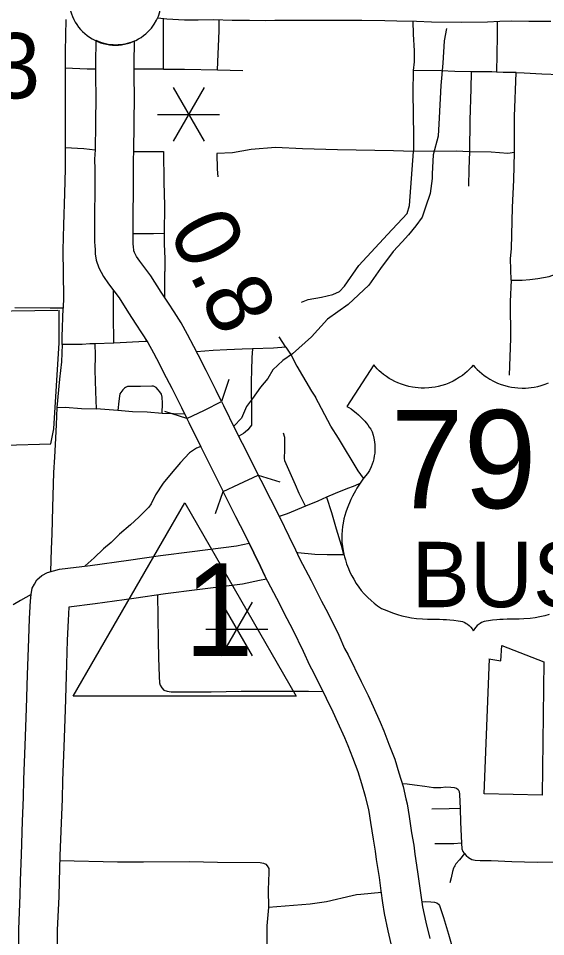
# Model space of a CAD drawing. Extents: x 61396 to 64680, y 55472 to 57605.
# Drawn here: x 62782.6 to 62889.2, y 55839.3 to 56024.7 of the extents above; entities that cross this region are included whole.
import ezdxf

# ---------------------------------------------------------------- set-up
doc = ezdxf.new("R2010")
doc.units = 0
for name, color, linetype in [('10', 7, 'Continuous'), ('15', 7, 'Continuous'), ('22', 7, 'Continuous'), ('24', 7, 'Continuous'), ('33', 7, 'Continuous'), ('34', 7, 'Continuous'), ('35', 7, 'Continuous'), ('37', 7, 'Continuous'), ('48', 7, 'Continuous'), ('57', 7, 'Continuous'), ('7', 7, 'Continuous'), ('R_Draft', 7, 'Continuous')]:
    doc.layers.add(name, color=color, linetype=linetype)

msp = doc.modelspace()

# ---------------------------------------------------------------- linework, layer by layer
at = {"layer": '10'}
for points in [[(62782.66, 55834.74), (62782.71, 55840.78), (62783.03, 55847.6), (62783.08, 55850.56), (62783.25, 55855.78), (62783.46, 55862.56), (62783.68, 55867.32), (62783.78, 55870.99), (62784, 55877.85), (62784.27, 55885.31), (62784.49, 55892.12), (62784.74, 55899.4), (62784.92, 55903.47), (62785.09, 55907.04), (62785.2, 55908.35), (62785.43, 55909.6), (62785.9, 55910.45), (62786.41, 55911.29), (62787.4, 55912.17), (62788.56, 55912.79), (62790.93, 55913.43), (62797.15, 55914.22), (62804.9, 55915.24), (62811.33, 55916.18), (62817.79, 55917.03), (62826.69, 55918.17), (62829.29, 55918.68), (62830.25, 55916.73), (62831.55, 55913.98), (62832.44, 55912.1), (62832.79, 55911.46)], [(62832.79, 55911.46), (62831.35, 55911.13), (62827.94, 55910.45), (62818.8, 55909.29), (62812.4, 55908.44), (62805.97, 55907.5), (62798.15, 55906.48), (62792.85, 55905.8), (62792.73, 55903.11), (62792.54, 55899.08), (62792.29, 55891.87), (62792.08, 55885.05), (62791.8, 55877.59), (62791.59, 55870.75), (62791.48, 55867.03), (62791.27, 55862.26), (62791.05, 55855.54), (62790.89, 55850.37), (62790.84, 55847.34), (62790.52, 55840.56), (62790.47, 55834.71)]]:
    msp.add_lwpolyline(points, dxfattribs=at)
at = {"layer": '15'}
for points in [[(62810.83, 56024.76), (62811.45, 56024.68), (62812.61, 56024.55), (62816.18, 56024.39), (62818.96, 56024.39), (62822.11, 56024.41), (62825.86, 56024.3), (62829.36, 56024.28), (62832.58, 56024.26), (62834.48, 56024.3), (62835.39, 56024.3)], [(62835.39, 56024.3), (62838.91, 56024.28), (62841.99, 56024.28), (62847.66, 56024.28), (62852.02, 56024.28), (62856.68, 56024.24), (62859.14, 56024.15), (62863.09, 56024.11), (62866.13, 56023.95), (62872.21, 56023.87), (62877.42, 56023.95), (62879.9, 56024.08), (62882.26, 56024.13), (62885.78, 56024.08), (62890.24, 56024.08)], [(62798.27, 56020.29), (62798.24, 56015.54), (62798.21, 56012.57), (62798.27, 56009.12), (62798.24, 56003.39), (62798.18, 55998.15), (62798.06, 55996.21), (62798.12, 55994.17), (62798.09, 55989.79), (62798.03, 55985.21), (62798.06, 55982.71), (62798, 55980.34), (62798.03, 55979.46), (62798.07, 55978.8), (62798.13, 55977.91), (62798.17, 55977.15), (62798.38, 55975.85), (62798.92, 55974.26), (62799.84, 55972.56), (62800.84, 55971.08), (62803.02, 55968.24), (62804.92, 55965.2), (62806.4, 55962.92), (62807.55, 55961.16), (62808.8, 55959.2), (62809.92, 55957.14), (62811.14, 55954.85), (62811.99, 55953.15), (62813.66, 55949.99), (62815.61, 55946.06), (62816.69, 55943.85)], [(62816.69, 55943.85), (62820.24, 55945.58), (62823.7, 55947.28), (62822.62, 55949.5), (62820.61, 55953.55), (62818.94, 55956.73), (62818.08, 55958.44), (62816.8, 55960.84), (62815.54, 55963.17), (62814.11, 55965.4), (62812.95, 55967.18), (62811.51, 55969.4), (62809.44, 55972.7), (62807.18, 55975.65), (62806.53, 55976.6), (62806.11, 55977.4), (62805.98, 55977.75), (62805.95, 55977.98), (62805.93, 55978.38), (62805.87, 55979.26), (62805.84, 55979.82), (62805.81, 55980.4), (62805.87, 55982.65), (62805.84, 55985.21), (62805.9, 55989.71), (62805.93, 55994.27), (62805.88, 55996.08), (62805.99, 55997.85), (62806.06, 56003.33), (62806.09, 56009.17), (62806.03, 56012.6), (62806.06, 56015.48), (62806.08, 56020.13)], [(62823.7, 55947.28), (62824.09, 55946.49), (62826.48, 55941.68), (62829.28, 55936.13), (62831.12, 55932.44)], [(62816.69, 55943.85), (62817.07, 55943.05), (62819.49, 55938.17), (62822.3, 55932.63), (62824.03, 55929.15)], [(62824.03, 55929.15), (62827.18, 55930.61), (62831.12, 55932.44), (62831.63, 55931.41), (62833.57, 55927.56), (62835.44, 55923.89), (62837.29, 55920.12), (62838.61, 55917.33), (62839.42, 55915.62), (62841.8, 55911.15), (62843.92, 55906.99), (62845.14, 55904.63), (62847.36, 55900.13), (62848.54, 55897.45), (62849.26, 55896.15), (62851.93, 55890.75), (62853.29, 55887.94), (62854.33, 55885.71), (62855.71, 55882.56), (62856.51, 55880.8), (62857.52, 55878.13), (62858.7, 55875.09), (62859.53, 55872.35), (62860.36, 55869.55), (62860.96, 55867.05), (62861.21, 55866.07), (62861.61, 55863.49), (62862.09, 55860.2), (62862.55, 55857.69), (62862.77, 55855.92), (62863.31, 55852.33), (62863.72, 55849.52), (62864.02, 55847.16), (62864.3, 55845.3), (62864.97, 55842.15), (62865.77, 55838.86)], [(62858.19, 55836.95), (62857.35, 55840.42), (62856.61, 55843.91), (62856.28, 55846.08), (62855.97, 55848.47), (62855.58, 55851.2), (62855.03, 55854.85), (62854.83, 55856.5), (62854.38, 55858.92), (62853.88, 55862.33), (62853.55, 55864.5), (62853.37, 55865.17), (62852.81, 55867.54), (62852.05, 55870.1), (62851.31, 55872.54), (62850.23, 55875.34), (62849.29, 55877.79), (62848.57, 55879.38), (62847.21, 55882.5), (62846.23, 55884.59), (62844.91, 55887.32), (62842.34, 55892.52), (62841.54, 55893.97), (62840.28, 55896.83), (62838.17, 55901.1), (62836.97, 55903.42), (62834.87, 55907.55), (62832.44, 55912.1), (62831.55, 55913.98), (62830.25, 55916.73), (62828.45, 55920.39), (62826.6, 55924.03), (62824.64, 55927.91), (62824.03, 55929.15)]]:
    msp.add_lwpolyline(points, dxfattribs=at)
for start, end in [(244.2549, 270), (270, 293.509)]:
    msp.add_arc((62802.34, 56028.73), 9.38, start, end, dxfattribs=at)
at = {"layer": '22'}
for points in [[(62874.55, 55954.64), (62874.14, 55954.18), (62873.75, 55953.78), (62873.3, 55953.36), (62872.82, 55952.95), (62872.35, 55952.58), (62871.79, 55952.19), (62871.18, 55951.81), (62870.49, 55951.43), (62869.62, 55951.03), (62868.95, 55950.76), (62868.19, 55950.52), (62867.49, 55950.34), (62866.85, 55950.21), (62866.18, 55950.1), (62865.56, 55950.04), (62864.7, 55950), (62864.01, 55950.01), (62863.41, 55950.04), (62862.84, 55950.1), (62862.26, 55950.19), (62861.53, 55950.34), (62860.86, 55950.52), (62860.03, 55950.78), (62859.34, 55951.06), (62858.7, 55951.35), (62858.12, 55951.65), (62857.59, 55951.97), (62856.99, 55952.36), (62856.44, 55952.76), (62855.97, 55953.15), (62855.57, 55953.5), (62855.16, 55953.9), (62854.77, 55954.32), (62854.44, 55954.69), (62849.03, 55946.32), (62849.42, 55946.09), (62849.88, 55945.79), (62850.32, 55945.48), (62850.9, 55945.03), (62851.36, 55944.63), (62851.77, 55944.24), (62852.19, 55943.82), (62852.62, 55943.34), (62852.93, 55942.97), (62853.23, 55942.58), (62853.54, 55942.15), (62853.84, 55941.7), (62854.12, 55941.16), (62854.33, 55940.51), (62854.49, 55939.87), (62854.6, 55939.18), (62854.67, 55938.53), (62854.69, 55937.91), (62854.68, 55937.34), (62854.64, 55936.87), (62854.56, 55936.3), (62854.46, 55935.76), (62854.31, 55935.19), (62854.14, 55934.68), (62853.92, 55934.11), (62853.57, 55933.37), (62853.21, 55932.79), (62852.77, 55932.27), (62852.24, 55931.59), (62851.81, 55930.99), (62851.41, 55930.39), (62851.04, 55929.81), (62850.73, 55929.29), (62850.46, 55928.8), (62850.16, 55928.21), (62849.83, 55927.53), (62849.54, 55926.86), (62849.33, 55926.36), (62849.1, 55925.73), (62848.83, 55924.95), (62848.62, 55924.3), (62848.43, 55923.59), (62848.24, 55922.77), (62848.12, 55922.04), (62848.04, 55921.28), (62847.99, 55920.45), (62847.98, 55919.67), (62848.02, 55918.9), (62848.11, 55918), (62848.25, 55917.15), (62848.39, 55916.51), (62848.54, 55915.95), (62848.72, 55915.31), (62848.97, 55914.51), (62849.33, 55913.55), (62849.64, 55912.84), (62849.99, 55912.11), (62850.39, 55911.4), (62850.9, 55910.57), (62851.42, 55909.82), (62851.93, 55909.16), (62852.51, 55908.49), (62853.26, 55907.71), (62853.89, 55907.13), (62854.55, 55906.58)], [(62874.55, 55954.64), (62874.96, 55954.18), (62875.35, 55953.78), (62875.8, 55953.36), (62876.28, 55952.95), (62876.75, 55952.58), (62877.31, 55952.19), (62877.92, 55951.81), (62878.61, 55951.43), (62879.48, 55951.03), (62880.16, 55950.76), (62880.91, 55950.52), (62881.61, 55950.34), (62882.25, 55950.21), (62882.92, 55950.1), (62883.54, 55950.04), (62884.4, 55950), (62885.09, 55950.01), (62885.69, 55950.04), (62886.26, 55950.1), (62886.84, 55950.19), (62887.57, 55950.34), (62888.24, 55950.52), (62889.07, 55950.78), (62889.76, 55951.06)], [(62854.55, 55906.58), (62855.22, 55906.07), (62856.04, 55905.53), (62857.06, 55905.07), (62858.26, 55904.62), (62859.24, 55904.3), (62860.12, 55904.05), (62861.11, 55903.82), (62862.04, 55903.65), (62863.05, 55903.51), (62864.31, 55903.41), (62865.28, 55903.37), (62866.11, 55903.38), (62866.91, 55903.37), (62867.72, 55903.34), (62868.48, 55903.3), (62869.15, 55903.26), (62869.81, 55903.2), (62870.65, 55903.12), (62871.47, 55903.01), (62871.96, 55902.95), (62872.37, 55902.87), (62872.86, 55902.66), (62873.14, 55902.51), (62873.39, 55902.34), (62873.73, 55902.07), (62874.05, 55901.74), (62874.31, 55901.41), (62874.55, 55901.02)], [(62889.86, 55904.3), (62888.98, 55904.05), (62887.99, 55903.82), (62887.06, 55903.65), (62886.05, 55903.51), (62884.79, 55903.41), (62883.82, 55903.37), (62882.99, 55903.38), (62882.19, 55903.37), (62881.38, 55903.34), (62880.62, 55903.3), (62879.95, 55903.26), (62879.29, 55903.2), (62878.45, 55903.12), (62877.63, 55903.01), (62877.14, 55902.95), (62876.73, 55902.87), (62876.24, 55902.66), (62875.96, 55902.51), (62875.71, 55902.34), (62875.37, 55902.07), (62875.05, 55901.74), (62874.79, 55901.41), (62874.55, 55901.02)]]:
    msp.add_lwpolyline(points, dxfattribs=at)
at = {"layer": '24'}
for start, end in [(315.0045, 135.0045), (135.0045, 315.0045)]:
    msp.add_arc((62802.24, 56028.63), 9.38, start, end, dxfattribs=at)
at = {"layer": '33'}
for p, q in [((62792.07, 56014.66), (62792.08, 55998.56)), ((62822.85, 56014.29), (62828.01, 56014.16)), ((62805.99, 55997.81), (62811.99, 55997.8)), ((62801.91, 55959.06), (62798.12, 55958.97)), ((62802.74, 55945.48), (62798.35, 55945.83))]:
    msp.add_line(p, q, dxfattribs=at)
for points in [[(62792.21, 56024.4), (62792.08, 56017.98), (62792.07, 56014.66)], [(62811.94, 56014.39), (62812, 56020.27), (62812, 56024.62)], [(62822.85, 56014.29), (62823.23, 56022.15), (62823.23, 56024.38)], [(62862.37, 56024.11), (62862.43, 56021.44), (62862.6, 56018.09), (62862.64, 56015.9), (62862.44, 56014.13)], [(62879.39, 56024.06), (62879.39, 56021.1), (62879.22, 56013.81)], [(62792.07, 56014.66), (62796.54, 56014.46), (62798.23, 56014.45)], [(62811.94, 56014.39), (62809.52, 56014.39), (62806.04, 56014.42)], [(62811.94, 56014.39), (62816.19, 56014.39), (62822.85, 56014.29)], [(62862.44, 56014.13), (62862.31, 56009.67), (62862.48, 56000.87), (62862.45, 55997.81)], [(62874.12, 56013.84), (62870.86, 56013.96), (62868.05, 56014.04), (62862.44, 56014.13)], [(62874.12, 56013.84), (62874.06, 56010.45), (62873.85, 56004.13), (62873.76, 55997.73)], [(62879.22, 56013.81), (62878.3, 56013.86), (62874.12, 56013.84)], [(62883.19, 56013.76), (62880.59, 56013.72), (62879.22, 56013.81)], [(62882.86, 55997.56), (62882.88, 56004.87), (62883.19, 56013.76)], [(62883.19, 56013.76), (62884.85, 56013.69), (62888.41, 56013.49), (62892.13, 56013.36)], [(62792.08, 55998.56), (62792.08, 55994.28), (62791.97, 55989.31), (62791.75, 55982.97), (62791.63, 55977.89), (62791.75, 55968.4), (62791.71, 55966.14)], [(62792.08, 55998.56), (62795.86, 55998.36), (62798.18, 55998.14)], [(62811.99, 55997.8), (62812.06, 55991.6), (62812.18, 55986.9), (62812.13, 55981.22)], [(62862.45, 55997.81), (62858.45, 55997.91), (62847.15, 55998.11), (62840.07, 55998.35), (62834.62, 55998.6), (62829.66, 55998.16), (62825.92, 55997.52), (62822.73, 55997.37)], [(62822.73, 55997.37), (62822.83, 55994.23), (62822.92, 55992.66)], [(62873.76, 55997.73), (62871.09, 55997.85), (62862.45, 55997.81)], [(62873.76, 55997.73), (62873.67, 55994.27), (62873.6, 55990.81)], [(62882.86, 55997.56), (62881.52, 55997.39), (62878.16, 55997.62), (62873.76, 55997.73)], [(62882.25, 55978.22), (62882.45, 55986.5), (62882.72, 55992.03), (62882.86, 55997.56)], [(62812.13, 55981.22), (62809.95, 55981.15), (62806.7, 55981.15), (62805.83, 55981.15)], [(62812.13, 55981.22), (62812.13, 55979.12), (62812.22, 55976.11), (62812.24, 55973.57)], [(62882.21, 55971.82), (62882.05, 55976.09), (62882.25, 55978.22)], [(62882.21, 55971.82), (62884.46, 55971.77), (62885.98, 55971.94), (62887.59, 55972.12), (62889.87, 55972.53), (62890.94, 55972.94), (62891.68, 55973.42), (62893.46, 55974.81), (62894.81, 55975.59), (62896.15, 55976.29), (62897.89, 55976.68), (62899.54, 55977.03), (62900.58, 55976.98), (62902.03, 55976.94), (62902.11, 55976.9)], [(62812.21, 55968.32), (62812.26, 55969.94), (62812.24, 55973.57)], [(62882.21, 55971.82), (62881.99, 55967.51), (62882.04, 55960.05)], [(62801.91, 55959.06), (62801.88, 55964.9), (62801.88, 55969.73)], [(62839.82, 55967.38), (62841.2, 55967.88), (62843.91, 55968.35)], [(62791.71, 55966.14), (62789.04, 55966.14), (62781.96, 55966.22)], [(62791.48, 55958.81), (62791.48, 55960.37), (62791.71, 55966.14)], [(62836.69, 55958.29), (62835.34, 55960.33)], [(62882.04, 55960.05), (62881.83, 55952.65)], [(62791.48, 55958.81), (62791.35, 55955.31), (62790.96, 55951.84), (62790.39, 55946.1)], [(62798.12, 55958.97), (62797.11, 55958.94), (62795.56, 55958.78), (62791.48, 55958.81)], [(62798.12, 55958.97), (62798.18, 55956.67), (62798.09, 55953.63), (62798.22, 55949.32), (62798.35, 55945.83)], [(62808.66, 55959.42), (62808.29, 55959.41), (62801.91, 55959.06)], [(62836.69, 55958.29), (62834.16, 55958.06), (62829.95, 55957.97)], [(62836.69, 55958.29), (62837.73, 55956.68), (62838.93, 55954.41), (62841.85, 55949.41), (62842.7, 55948.19)], [(62829.95, 55957.97), (62827.85, 55957.88), (62824.78, 55957.72), (62822.01, 55957.62), (62818.64, 55957.32)], [(62829.95, 55957.97), (62829.81, 55956.18), (62829.78, 55953.55), (62829.65, 55951.41), (62829.76, 55944.32), (62829.73, 55942.94), (62829.73, 55942.52), (62829.47, 55942.16), (62829.03, 55941.61), (62828.48, 55941.09), (62828.11, 55940.83), (62827.17, 55940.31)], [(62811.69, 55944.88), (62811.75, 55946.98), (62811.7, 55948.16), (62811.55, 55948.8), (62811.24, 55949.23), (62810.88, 55949.69), (62810.48, 55950.12), (62809.96, 55950.38), (62809.58, 55950.41), (62807.33, 55950.3), (62806.05, 55950.3), (62805.29, 55950.33), (62804.72, 55950.33), (62804.32, 55950.15), (62804.06, 55950.02), (62803.75, 55949.64), (62803.32, 55949.13), (62803.17, 55948.82), (62803.09, 55948.36), (62802.94, 55947.36), (62802.74, 55945.48)], [(62852.4, 55931.79), (62851.31, 55933.28), (62847.34, 55939.89), (62845.8, 55942.31), (62842.7, 55948.19)], [(62790.39, 55946.1), (62790.3, 55942.58), (62790.07, 55938.59), (62789.97, 55936.05), (62789.77, 55932.98), (62789.57, 55925.89), (62789.44, 55920.58), (62789.27, 55917.52), (62789.17, 55912.95)], [(62790.39, 55946.1), (62792.13, 55946.15), (62795.37, 55945.92), (62798.35, 55945.83)], [(62811.69, 55944.88), (62808.64, 55945.14), (62805.7, 55945.22), (62802.74, 55945.48)], [(62816.25, 55944.74), (62811.69, 55944.88)], [(62840.64, 55926.2), (62839.41, 55928.72), (62838.62, 55930.5), (62836.47, 55935.31), (62836.39, 55935.83), (62836.47, 55937.46), (62836.45, 55940.02), (62836.2, 55940.89)], [(62851.63, 55930.72), (62850.6, 55930.3), (62848.83, 55929.58), (62846.64, 55928.72), (62844.91, 55927.96)], [(62844.91, 55927.96), (62843.18, 55927.18), (62840.64, 55926.2)], [(62844.91, 55927.96), (62845.93, 55924.92), (62846.88, 55921.62), (62847.88, 55918.27), (62848.33, 55916.33)], [(62840.64, 55926.2), (62836.92, 55924.64), (62835.32, 55924.11)], [(62848.33, 55916.33), (62845.01, 55916.36), (62842.55, 55916.44), (62839.14, 55916.72), (62838.89, 55916.73)], [(62810.75, 55908.2), (62810.81, 55903.91), (62810.91, 55898.91), (62810.98, 55895.61), (62811.09, 55891.8), (62811.13, 55890.5), (62811.28, 55890.02), (62811.61, 55889.46), (62812.02, 55889.02), (62812.72, 55888.8), (62813.54, 55888.65), (62815.5, 55888.65), (62821.62, 55888.65), (62827.69, 55888.8), (62835.03, 55888.8), (62841.29, 55888.8), (62844.22, 55888.72)], [(62860.18, 55870.16), (62861.18, 55870.09), (62862.65, 55869.92), (62864.77, 55869.62), (62866.52, 55869.34), (62867.97, 55869.37), (62869.01, 55869.49), (62869.99, 55869.44), (62870.71, 55869.37), (62871.14, 55869.22), (62871.51, 55868.99), (62871.71, 55868.57), (62871.79, 55867.97), (62871.88, 55865.13)], [(62871.88, 55865.13), (62869.66, 55865.05), (62866.17, 55865)], [(62871.88, 55865.13), (62871.96, 55862.38), (62872.2, 55858.13)], [(62872.2, 55858.13), (62870.62, 55858.01), (62868.61, 55857.99), (62866.81, 55858.02)], [(62872.2, 55858.13), (62872.27, 55856.95), (62872.44, 55856.46), (62872.63, 55856.15), (62872.79, 55856.02)], [(62791.03, 55854.6), (62802.66, 55854.38), (62807.9, 55854.38), (62817.23, 55854.42), (62822.88, 55854.32), (62831.49, 55854.23), (62832.2, 55854.08), (62832.63, 55853.86), (62832.91, 55853.52), (62833.22, 55853.03), (62833.25, 55852.22), (62833.09, 55848.71), (62833.16, 55845.12)], [(62872.79, 55856.02), (62871.8, 55854.76), (62871.03, 55853.93), (62870.81, 55853.56), (62870.71, 55853.36), (62870.59, 55853.09), (62870.34, 55852.38), (62870.1, 55851.15), (62869.83, 55850.11)], [(62872.79, 55856.02), (62873.09, 55855.64), (62873.62, 55855.22), (62874.28, 55854.81), (62874.93, 55854.67), (62875.95, 55854.62), (62878.19, 55854.65), (62882.34, 55854.45), (62887.48, 55854.3), (62892.27, 55854.34), (62896.91, 55854.87), (62900.71, 55855.17), (62902.53, 55855.25), (62905.88, 55855.25), (62909.91, 55854.98), (62913.64, 55854.87), (62917.9, 55854.6), (62921.51, 55854.49), (62926.83, 55854.26), (62931.89, 55854.03), (62933.41, 55853.96), (62936.68, 55853.3)], [(62856.01, 55848.16), (62851.84, 55847.79), (62850.97, 55847.66), (62850.07, 55847.48), (62844.9, 55846.27), (62841.63, 55845.8), (62833.16, 55845.12)], [(62833.16, 55845.12), (62832.83, 55841.41), (62832.87, 55836.08), (62833.05, 55824.42), (62833.05, 55818.7), (62832.91, 55815.34)], [(62864.15, 55846.26), (62864.8, 55846.34), (62865.95, 55846.31), (62866.69, 55846.21), (62867.22, 55846.06), (62867.53, 55845.84), (62867.72, 55845.53), (62868.52, 55843.14), (62869.58, 55839.76), (62870.66, 55835.8), (62870.65, 55834.85), (62870.58, 55834.16), (62870.33, 55833.65), (62869.99, 55833.26), (62869.67, 55832.92), (62869.21, 55832.75), (62867.47, 55832.26)]]:
    msp.add_lwpolyline(points, dxfattribs=at)
at = {"layer": '34'}
msp.add_lwpolyline([(62843.91, 55968.35), (62846.21, 55968.91), (62847.54, 55969.51), (62848.55, 55970.56), (62851.43, 55974.77), (62857.2, 55981.04), (62861.18, 55985.29), (62861.68, 55986.85), (62862.45, 55997.81)], dxfattribs=at)
at = {"layer": '35'}
for points in [[(62869.11, 56022.59), (62868.68, 56020.11), (62868.42, 56015.64), (62868.03, 56011.11), (62867.63, 56004.56), (62867.44, 56000.9), (62866.47, 55997.12), (62866.24, 55993.3), (62866.24, 55992.36), (62865.87, 55989.28), (62864.9, 55986.56), (62864.26, 55984.53), (62862.92, 55982.78), (62861.49, 55980.98), (62860.16, 55979.55), (62858.36, 55977.62), (62855.82, 55974.16), (62853.45, 55970.77), (62849.31, 55966.88), (62845.12, 55963.92), (62841.87, 55960.33), (62838.01, 55956.9), (62836.08, 55955.61), (62834.09, 55953.73), (62833.06, 55951.94), (62831.59, 55950.23), (62829.96, 55947.89), (62828.71, 55946.32), (62827.74, 55943.97), (62826.17, 55942.32)], [(62819.53, 55938.2), (62818.65, 55937.85), (62817.25, 55936.96), (62815.38, 55934.99), (62813.52, 55932.79), (62811.87, 55930.79), (62810.33, 55928.49), (62809.49, 55926.64), (62808.98, 55925.97), (62806.96, 55923.96), (62805.3, 55922.37), (62803.11, 55920.51), (62801.39, 55918.82), (62799.84, 55917.54), (62797.94, 55915.73), (62796.12, 55914.1)], [(62785.24, 55908.36), (62783.05, 55907.12), (62781.61, 55906.25)]]:
    msp.add_lwpolyline(points, dxfattribs=at)
at = {"layer": '37'}
for points in [[(62825.2, 55951.72), (62823.7, 55947.28)], [(62816.69, 55943.85), (62812.26, 55945.31)], [(62831.12, 55932.44), (62835.48, 55931.05)], [(62822.5, 55924.72), (62824.03, 55929.15)]]:
    msp.add_lwpolyline(points, dxfattribs=at)
at = {"layer": '48'}
for p, q in [((62820.16, 56010.69), (62813.91, 55999.87)), ((62813.91, 56010.69), (62820.16, 55999.87)), ((62810.78, 56005.28), (62823.28, 56005.28)), ((62829.89, 55906.76), (62823.64, 55895.94)), ((62823.64, 55906.76), (62829.89, 55895.94)), ((62820.52, 55901.35), (62833.02, 55901.35))]:
    msp.add_line(p, q, dxfattribs=at)
at = {"layer": '57'}
msp.add_lwpolyline([(62790.63, 55965.68), (62771.87, 55965.44), (62771.55, 55965.2), (62771.15, 55964.24), (62771.07, 55940.3), (62769.55, 55940.22), (62769.47, 55932.79), (62771.55, 55932.47), (62779.93, 55932.23), (62780.01, 55938.46), (62789.2, 55938.78), (62789.84, 55941.81), (62790.87, 55959.14), (62790.89, 55965.76)], dxfattribs=at)
at = {"layer": '7'}
for points in [[(62877.7, 55895.34), (62880.09, 55894.92), (62880.29, 55898.03), (62888.8, 55894.72), (62888.49, 55867.79), (62876.77, 55868.07)], [(62876.77, 55868.07), (62877.83, 55895.32)]]:
    msp.add_lwpolyline(points, dxfattribs=at)
at = {"layer": 'R_Draft'}
msp.add_lwpolyline([(62816.27, 55926.81), (62838.79, 55887.8), (62793.74, 55887.8), (62816.27, 55926.82)], dxfattribs=at)

# ---------------------------------------------------------------- texts
at = {"layer": '22'}
for s, height, p in [('79', 19.8, (62857.88, 55925.76)), ('BUS', 13.2, (62862.08, 55905.77))]:
    msp.add_text(s, height=height, dxfattribs=at).set_placement(p)
at = {"layer": '48'}
for s, rotation, p in [('0.3', 359.933, (62762.49, 56008.53)), ('0.8', 295.5566, (62812.84, 55982.02))]:
    msp.add_text(s, height=13.2, rotation=rotation, dxfattribs=at).set_placement(p)
at = {"layer": 'R_Draft'}
msp.add_text('1', height=18.75, dxfattribs=at).set_placement((62816.17, 55895.91))

doc.saveas('drawing.dxf')
